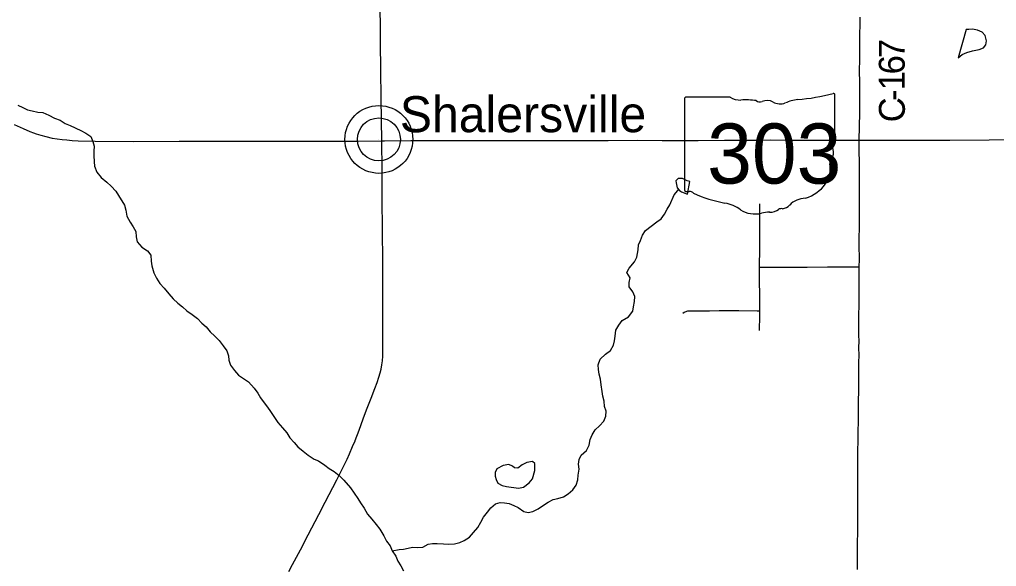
# Model space of a CAD drawing. Extents: x 0 to 34, y 0 to 22.
# Drawn here: x 15.949 to 18.09, y 17.236 to 18.436 of the extents above; entities that cross this region are included whole.
import ezdxf

# ---------------------------------------------------------------- set-up
doc = ezdxf.new("R2010")
doc.units = 0
for name, color, linetype in [('GM_X_County_Road', 7, 'Continuous'), ('GM_X_County_Road_Text', 7, 'Continuous'), ('GM_X_Minor_Lake', 7, 'Continuous'), ('GM_X_Minor_River', 7, 'Continuous'), ('GM_X_State_Location', 7, 'Continuous'), ('GM_X_State_Route', 7, 'Continuous'), ('GM_X_State_Shield', 7, 'Continuous'), ('GM_X_Township_Road', 7, 'Continuous'), ('GM_X_Unincorporated', 7, 'Continuous'), ('GM_X_Unincorporated_Location', 7, 'Continuous'), ('GM_X_Unincorporated_Text', 7, 'Continuous')]:
    doc.layers.add(name, color=color, linetype=linetype)

msp = doc.modelspace()

# ---------------------------------------------------------------- linework, layer by layer
at = {"layer": 'GM_X_County_Road'}
for points in [[(17.7892, 18.1713), (17.79, 18.2311), (17.7902, 18.2746), (17.7903, 18.2982), (17.7899, 18.3224), (17.7902, 18.3491), (17.7904, 18.3765), (17.7906, 18.3945), (17.7906, 18.4026), (17.7907, 18.4249), (17.7908, 18.4405)], [(17.789, 17.893), (17.7892, 17.8975), (17.7895, 17.905), (17.7893, 17.923), (17.7891, 17.9279), (17.789, 17.9433), (17.7892, 17.961), (17.7893, 17.9746), (17.7894, 17.9826), (17.7895, 18.0011), (17.7893, 18.0123), (17.7895, 18.049), (17.7895, 18.1155), (17.7892, 18.1546), (17.7891, 18.1664), (17.7892, 18.1713)], [(17.7849, 17.2294), (17.7851, 17.2381), (17.7854, 17.2561), (17.7853, 17.2729), (17.7854, 17.2847), (17.786, 17.3145), (17.786, 17.3269), (17.7862, 17.3425), (17.7862, 17.3536), (17.7862, 17.3605), (17.7861, 17.3723), (17.7859, 17.376), (17.7859, 17.3917), (17.7859, 17.4052), (17.7859, 17.4094), (17.7858, 17.4135), (17.7857, 17.422), (17.7856, 17.4361), (17.7856, 17.4478), (17.7856, 17.4559), (17.7858, 17.4734), (17.7859, 17.4939), (17.7863, 17.5074), (17.7866, 17.5242), (17.7873, 17.5621), (17.7872, 17.5683), (17.7876, 17.6033), (17.7879, 17.6172), (17.7881, 17.6316), (17.7879, 17.6565), (17.7883, 17.6686), (17.7884, 17.6831), (17.7887, 17.6993), (17.7884, 17.7154), (17.7885, 17.7313), (17.7883, 17.7427), (17.7883, 17.7707), (17.7888, 17.826), (17.7889, 17.8639), (17.789, 17.893)]]:
    msp.add_lwpolyline(points, dxfattribs=at)
at = {"layer": 'GM_X_Minor_Lake'}
for p, q in [((18.0232, 18.4138), (18.006, 18.3517)), ((17.4128, 18.0528), (17.4175, 18.0802)), ((17.0158, 17.4116), (17.0421, 17.4079))]:
    msp.add_line(p, q, dxfattribs=at)
for points in [[(18.006, 18.3517), (18.0147, 18.3587), (18.0245, 18.3633), (18.0373, 18.3669), (18.052, 18.3697), (18.0615, 18.3736), (18.0663, 18.3802), (18.0681, 18.3893), (18.0653, 18.4003), (18.0581, 18.4082), (18.0485, 18.4126), (18.0375, 18.4144), (18.0292, 18.4135), (18.0232, 18.4138)], [(17.4175, 18.0802), (17.4121, 18.082), (17.4019, 18.0868), (17.3924, 18.0871), (17.3871, 18.0821), (17.3876, 18.0775), (17.39, 18.0665), (17.3949, 18.0605), (17.3995, 18.0575), (17.4128, 18.0528)], [(17.0421, 17.4079), (17.0534, 17.4098), (17.0657, 17.4198), (17.0732, 17.4286), (17.0783, 17.4466), (17.0782, 17.4617), (17.0728, 17.4662), (17.0603, 17.4642), (17.0505, 17.4588), (17.0404, 17.4514), (17.0332, 17.4525), (17.0294, 17.4562), (17.021, 17.4596), (17.0089, 17.4575), (16.995, 17.4505), (16.9909, 17.4421), (16.991, 17.4345), (16.9933, 17.4266), (16.9972, 17.4186), (17.0063, 17.4138), (17.0158, 17.4116)]]:
    msp.add_lwpolyline(points, dxfattribs=at)
at = {"layer": 'GM_X_Minor_River'}
for points in [[(15.9449, 18.2479), (15.9556, 18.2427), (15.9659, 18.2379), (15.9765, 18.2354), (15.989, 18.2325), (15.9993, 18.2319), (16.013, 18.2259), (16.0252, 18.2196), (16.0373, 18.2148), (16.0484, 18.2077), (16.0594, 18.2029), (16.083, 18.1926), (16.0937, 18.1866), (16.1048, 18.1792), (16.1091, 18.1678), (16.1122, 18.158), (16.1116, 18.147), (16.1113, 18.1375), (16.1122, 18.1238), (16.1131, 18.1143), (16.1181, 18.1007), (16.1277, 18.0891), (16.1396, 18.0789), (16.1492, 18.0699), (16.1599, 18.0594), (16.1653, 18.0496), (16.1784, 18.0285), (16.1819, 18.0175), (16.184, 18.0046), (16.1913, 17.9911), (16.1979, 17.9813), (16.2033, 17.9707), (16.2045, 17.9593), (16.2066, 17.9483), (16.2169, 17.9363), (16.2287, 17.9284), (16.2364, 17.9187), (16.237, 17.9058), (16.2386, 17.8955), (16.2433, 17.8804), (16.2491, 17.8683), (16.2564, 17.8566), (16.2653, 17.8468), (16.276, 17.8344), (16.2856, 17.8232), (16.2952, 17.8138), (16.3055, 17.8052), (16.315, 17.7969), (16.3269, 17.7887), (16.3383, 17.7797), (16.3479, 17.77), (16.3575, 17.7617), (16.3667, 17.7508), (16.3766, 17.7414), (16.3862, 17.7317), (16.3951, 17.72), (16.4028, 17.7087), (16.4067, 17.6981), (16.4075, 17.6886), (16.4107, 17.6776), (16.4199, 17.666), (16.4284, 17.6554), (16.4394, 17.6487), (16.4501, 17.6409), (16.4631, 17.627), (16.4708, 17.6161), (16.477, 17.6063), (16.4847, 17.5953), (16.492, 17.5856), (16.4989, 17.5758), (16.5074, 17.5626), (16.5147, 17.5516), (16.5251, 17.54), (16.5343, 17.5295), (16.5408, 17.5181), (16.5504, 17.508), (16.5585, 17.4982), (16.5703, 17.4892), (16.5814, 17.4799), (16.594, 17.4713), (16.6035, 17.4676)], [(16.7652, 17.2705), (16.7803, 17.273), (16.7901, 17.2738), (16.8003, 17.2762), (16.8101, 17.2782), (16.8211, 17.278), (16.8325, 17.2781), (16.8442, 17.2851), (16.854, 17.2867), (16.8638, 17.2865), (16.8779, 17.2859), (16.8896, 17.2852), (16.9017, 17.2854), (16.9134, 17.2886), (16.9232, 17.2928), (16.9349, 17.3006), (16.9435, 17.3106), (16.9528, 17.3217), (16.9595, 17.3331), (16.9658, 17.3446), (16.9744, 17.3553), (16.9815, 17.3649), (16.992, 17.3738), (17.0018, 17.3762), (17.0113, 17.3755), (17.0216, 17.3745), (17.0318, 17.3697), (17.0413, 17.3656), (17.0536, 17.3563), (17.0631, 17.3545), (17.0736, 17.3569), (17.0853, 17.3627), (17.0973, 17.3708), (17.1075, 17.377), (17.1184, 17.3828), (17.1282, 17.3849), (17.1407, 17.3888), (17.1512, 17.3954), (17.1614, 17.4042), (17.1684, 17.4146), (17.1725, 17.426), (17.1731, 17.4366), (17.1749, 17.4492), (17.1736, 17.4606), (17.1754, 17.4709), (17.1798, 17.4804), (17.1915, 17.4904), (17.197, 17.5019), (17.1991, 17.5148), (17.2036, 17.5251), (17.2103, 17.5358), (17.22, 17.5443), (17.2294, 17.5547), (17.2334, 17.5661), (17.2341, 17.5764), (17.2309, 17.587), (17.2296, 17.5987), (17.2273, 17.6093), (17.2256, 17.6195), (17.2232, 17.6343), (17.2219, 17.6468), (17.2191, 17.6578), (17.2175, 17.6684), (17.217, 17.6783), (17.2214, 17.6905), (17.2327, 17.7017), (17.2436, 17.7098), (17.2502, 17.7216), (17.2528, 17.7311), (17.2542, 17.741), (17.2556, 17.7547), (17.2619, 17.7654), (17.2697, 17.7754), (17.2836, 17.7839), (17.293, 17.7962), (17.294, 17.8057), (17.2961, 17.8171), (17.2968, 17.8281), (17.2925, 17.8383), (17.2844, 17.8496), (17.2847, 17.8591), (17.2872, 17.869), (17.2795, 17.8807), (17.2847, 17.8906), (17.2967, 17.9044), (17.3019, 17.9144), (17.3047, 17.9304), (17.3054, 17.9414), (17.3098, 17.9509), (17.3142, 17.9624), (17.3206, 17.9727), (17.3326, 17.9827), (17.3453, 17.992), (17.3551, 17.9985), (17.3622, 18.0089), (17.3681, 18.02), (17.3737, 18.0295), (17.3833, 18.0509), (17.3912, 18.0605), (17.3928, 18.0631)], [(16.6035, 17.4676), (16.6176, 17.4583), (16.6272, 17.4512), (16.6379, 17.4441), (16.6493, 17.4355), (16.6597, 17.4257), (16.6739, 17.4084), (16.6823, 17.3967), (16.6897, 17.3854), (16.6962, 17.3756), (16.7039, 17.364), (16.7112, 17.3508), (16.7205, 17.3398), (16.7304, 17.3278), (16.7381, 17.3176), (16.747, 17.3033), (16.7528, 17.2916), (16.7609, 17.2815), (16.7652, 17.2705), (16.7733, 17.2584), (16.7779, 17.2475), (16.7845, 17.2373), (16.7899, 17.2264)]]:
    msp.add_lwpolyline(points, dxfattribs=at)
at = {"layer": 'GM_X_State_Route'}
for points in [[(16.7425, 18.1697), (16.7409, 18.2627), (16.7404, 18.3254), (16.7398, 18.3845), (16.7389, 18.4957), (16.7384, 18.5326), (16.7382, 18.5588)], [(15.9371, 18.2056), (15.9563, 18.1967), (15.971, 18.1903), (15.979, 18.1869), (15.985, 18.1849), (15.995, 18.1818), (16.0064, 18.1788), (16.0203, 18.1756), (16.0312, 18.1738), (16.0423, 18.1723), (16.0522, 18.1715), (16.064, 18.1705), (16.077, 18.1697), (16.1141, 18.1687), (16.1986, 18.1685), (16.2986, 18.1688), (16.3823, 18.169)], [(16.3823, 18.169), (16.4352, 18.1692), (16.4879, 18.1692), (16.5482, 18.1689), (16.6904, 18.169), (16.7425, 18.1697)], [(16.6839, 17.5118), (16.6842, 17.5127), (16.6928, 17.5354), (16.702, 17.5598), (16.7094, 17.5795), (16.7191, 17.6051), (16.7274, 17.6265), (16.7325, 17.6399), (16.7363, 17.651), (16.7393, 17.6611), (16.7412, 17.6689), (16.743, 17.6786), (16.7441, 17.6872), (16.7448, 17.6971), (16.7452, 17.7107), (16.7448, 17.8085), (16.7447, 17.8918), (16.744, 17.9868), (16.7437, 18.029), (16.7435, 18.0753), (16.7434, 18.1056), (16.7425, 18.1697)], [(16.7425, 18.1697), (16.7482, 18.1698), (16.806, 18.17), (16.8563, 18.17), (16.9091, 18.1701), (16.9557, 18.1701), (17.0122, 18.1702), (17.0514, 18.1702), (17.1415, 18.1705), (17.1857, 18.1703), (17.2385, 18.1706), (17.3037, 18.1708), (17.3571, 18.1707), (17.3944, 18.1707), (17.4361, 18.1707), (17.4939, 18.1712), (17.5715, 18.1714), (17.5945, 18.1715), (17.6336, 18.1714), (17.7713, 18.1713), (17.7892, 18.1713), (17.7986, 18.1713), (17.8805, 18.1713), (17.9874, 18.1714), (18.0738, 18.1718), (18.1731, 18.1723)], [(16.6188, 17.3773), (16.644, 17.4261), (16.653, 17.4438), (16.6565, 17.4507), (16.6666, 17.4716), (16.6719, 17.4829), (16.6787, 17.4989), (16.6839, 17.5118)], [(16.5386, 17.2253), (16.5469, 17.2406), (16.5642, 17.2729), (16.5813, 17.3053), (16.6046, 17.3499), (16.6188, 17.3773)]]:
    msp.add_lwpolyline(points, dxfattribs=at)
at = {"layer": 'GM_X_State_Shield'}
for p, q in [((17.506, 18.2654), (17.4095, 18.2654)), ((17.7358, 18.1657), (17.7358, 18.2704)), ((17.4062, 18.2619), (17.4062, 18.0618)), ((17.7358, 18.1657), (17.7358, 18.1657))]:
    msp.add_line(p, q, dxfattribs=at)
for centre, major_axis, start_param, end_param in [((17.41, 18.2624), (0.00382, 0), 1.712693, 3.28349), ((17.529, 18.2886), (0.037, 0), 4.042523, 4.731795), ((17.6184, 18.5382), (0.3495, 0), 4.814394, 5.042369), ((17.7322, 18.2708), (0.00367, 0), 6.141152, 7.989035), ((17.5413, 18.153), (0.133, 0), 1.404758, 1.657858), ((17.5714, 18.2634), (0.0107, 0), 3.836095, 5.185415), ((17.5871, 18.2403), (0.0222, 0), 0.950623, 2.079405), ((17.6158, 18.272), (0.0267, 0), 4.081561, 5.145723), ((17.663, 18.2043), (0.0703, 0), 1.699011, 2.107814), ((17.735, 18.158), (0.00568, 0), 1.883978, 3.671073), ((17.7319, 18.1653), (0.00393, 0), 5.05454, 6.418171), ((17.6988, 18.1447), (0.0341, 0), 5.934695, 6.695948), ((17.638, 18.1085), (0.0874, 0), 5.101752, 6.440018), ((17.749, 18.1219), (0.0248, 0), 2.387724, 3.262537), ((17.41, 18.0614), (0.00385, 0), 3.00124, 4.508301), ((17.4106, 18.0819), (0.0294, 0), 4.665946, 4.897461), ((17.4166, 18.0503), (0.0106, 0), 0.519207, 1.627899), ((17.5505, 18.2301), (0.2524, 0), 4.195997, 4.488961), ((17.4752, 17.9719), (0.079, 0), 0.823519, 1.323587), ((17.6142, 18.0424), (0.0282, 0), 4.937069, 5.64225), ((17.6748, 18.0056), (0.0479, 0), 1.647645, 2.488434), ((17.5606, 18.0493), (0.0501, 0), 4.026481, 4.996735), ((17.5896, 17.9801), (0.0412, 0), 1.495662, 1.94098), ((17.5932, 18.0343), (0.0267, 0), 4.691044, 5.507374), ((17.6174, 18.0149), (0.00752, 0), 1.147584, 2.315152)]:
    msp.add_ellipse(centre, major_axis=major_axis, ratio=0.8, start_param=start_param, end_param=end_param, dxfattribs=at)
at = {"layer": 'GM_X_Township_Road'}
for points in [[(17.5707, 17.8924), (17.5707, 17.8941), (17.571, 17.9326), (17.5711, 17.9593), (17.5711, 17.976), (17.5711, 17.9996), (17.5713, 18.0232), (17.5713, 18.0313)], [(17.5711, 17.797), (17.5711, 17.8196), (17.5708, 17.8314), (17.5706, 17.8624), (17.5706, 17.8748), (17.5707, 17.8924)], [(17.5707, 17.8924), (17.5768, 17.8924), (17.6066, 17.8924), (17.675, 17.8926), (17.7197, 17.8931), (17.789, 17.893)], [(17.4025, 17.7916), (17.4056, 17.7936), (17.4095, 17.7955), (17.4113, 17.7962), (17.4131, 17.7965), (17.418, 17.7969), (17.4323, 17.7969), (17.4503, 17.7968), (17.4609, 17.7969), (17.4819, 17.7974), (17.5024, 17.7976), (17.5254, 17.7973), (17.5651, 17.797), (17.5711, 17.797)], [(17.5707, 17.7538), (17.5711, 17.7855), (17.5711, 17.797)]]:
    msp.add_lwpolyline(points, dxfattribs=at)
at = {"layer": 'GM_X_Unincorporated'}
for radius in [0.0744, 0.0472]:
    msp.add_circle((16.7362, 18.1727), radius, dxfattribs=at)
at = {"layer": 'GM_X_Unincorporated_Location'}
msp.add_line((16.7362, 18.1727), (16.7362, 18.1727), dxfattribs=at)

# ---------------------------------------------------------------- texts
at = {"layer": 'GM_X_County_Road_Text'}
for s, rotation, p in [('7', 89.3599, (17.8887, 18.3502)), ('6', 89.8074, (17.8886, 18.3153)), ('1', 90.1249, (17.8887, 18.2804)), ('-', 90.3279, (17.8888, 18.2571)), ('C', 90.4098, (17.8892, 18.2105))]:
    msp.add_text(s, height=0.0568, rotation=rotation, dxfattribs=at).set_placement(p)
at = {"layer": 'GM_X_State_Location'}
for s in ['s', 'r']:
    msp.add_text(s, height=0.000189, dxfattribs=at).set_placement((17.5673, 18.1486))
msp.add_text('303', height=0.000189, rotation=0, dxfattribs=at).set_placement((17.5005, 18.1348))
at = {"layer": 'GM_X_State_Shield'}
msp.add_text('303', height=0.13184, dxfattribs=at).set_placement((17.4557, 18.0759))
at = {"layer": 'GM_X_Unincorporated_Text'}
msp.add_text('Shalersville', height=0.078977, rotation=0, dxfattribs=at).set_placement((16.7821, 18.1886))

doc.saveas('drawing.dxf')
